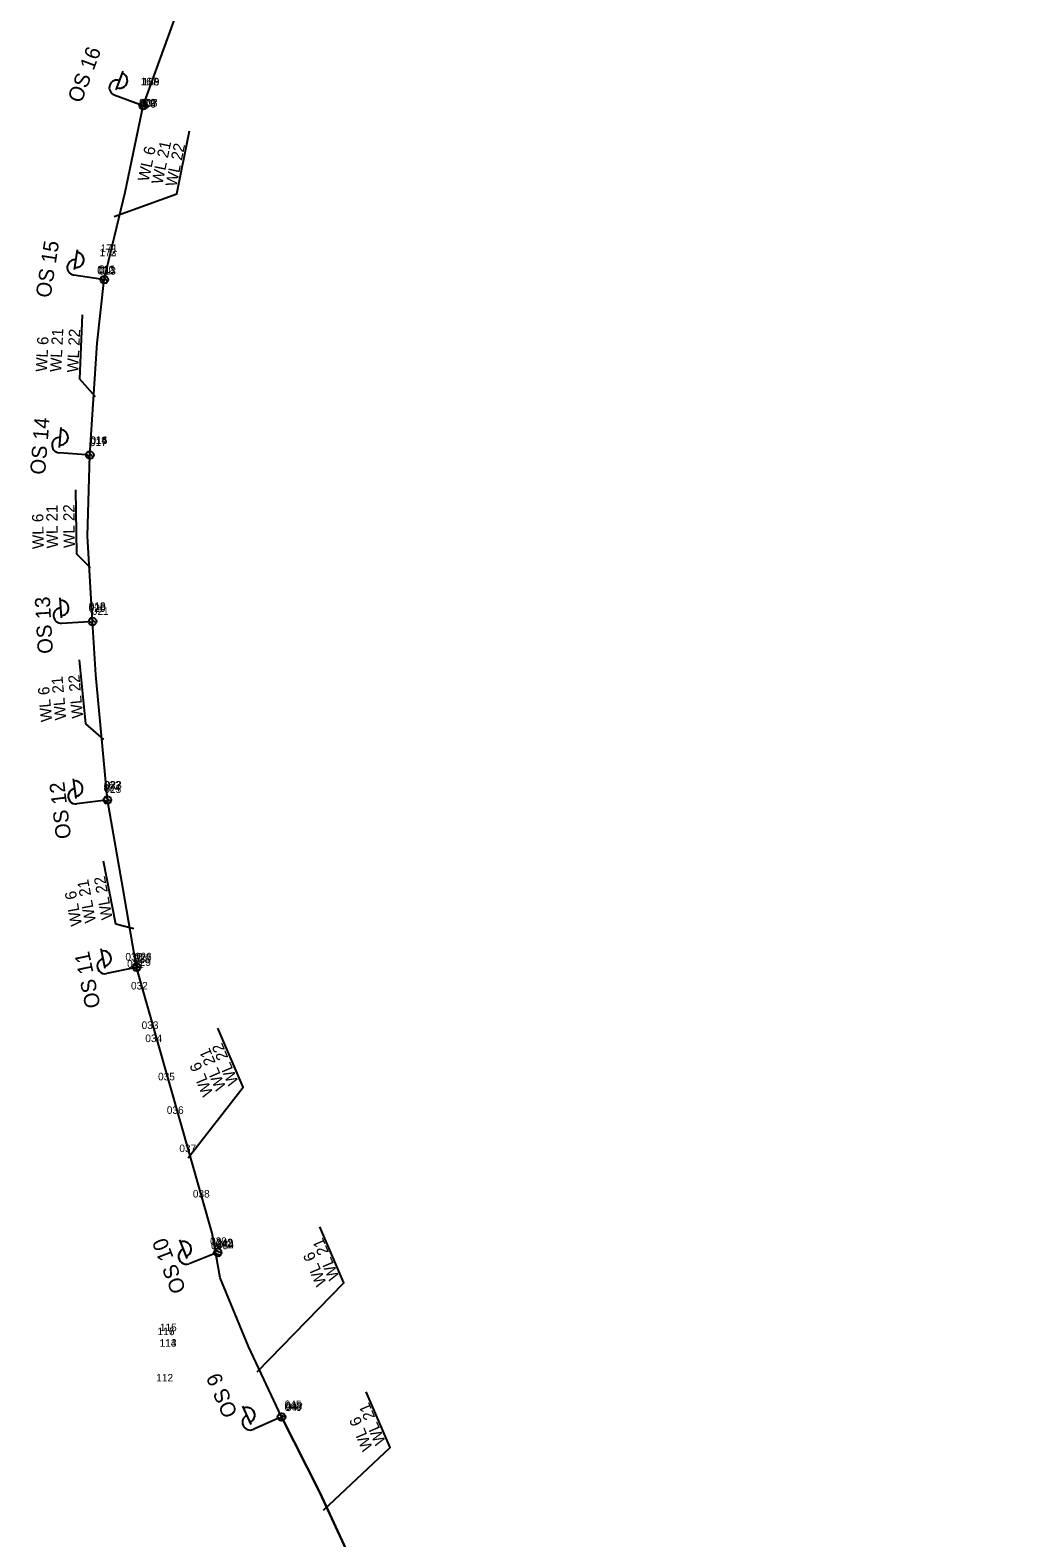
# Model space of a CAD drawing. Extents: x -695448 to -695200, y -1124997 to -1123857.
# Drawn here: x -695447.6 to -695315.9, y -1124800.8 to -1124601.1 of the extents above; entities that cross this region are included whole.
import ezdxf

# ---------------------------------------------------------------- set-up
doc = ezdxf.new("R2010")
doc.units = 0
doc.layers.add('Vrstva 26', color=7, linetype='Continuous')

msp = doc.modelspace()

# ---------------------------------------------------------------- linework, layer by layer
at = {"layer": 'Vrstva 26'}
for p, q in [((-695436.23, -1124608.98), (-695435.31, -1124606.48)), ((-695433.12, -1124610.89), (-695436.48, -1124609.65)), ((-695432.31, -1124611.45), (-695432.72, -1124610.56)), ((-695432.67, -1124611.58), (-695433.05, -1124610.76)), ((-695441.75, -1124632.79), (-695441.36, -1124630.17)), ((-695438.31, -1124634.03), (-695441.85, -1124633.5)), ((-695437.73, -1124634.61), (-695438.27, -1124633.89)), ((-695437.4, -1124634.41), (-695437.98, -1124633.63)), ((-695443.75, -1124656.33), (-695443.54, -1124653.68)), ((-695440.23, -1124657.32), (-695443.8, -1124657.04)), ((-695439.61, -1124657.85), (-695440.2, -1124657.17)), ((-695439.3, -1124657.63), (-695439.93, -1124656.89)), ((-695443.49, -1124678.94), (-695443.65, -1124676.28)), ((-695439.87, -1124679.43), (-695443.44, -1124679.65)), ((-695439.18, -1124679.87), (-695439.86, -1124679.28)), ((-695438.9, -1124679.61), (-695439.63, -1124678.96)), ((-695441.54, -1124702.87), (-695441.88, -1124700.23)), ((-695437.9, -1124703.12), (-695441.45, -1124703.58)), ((-695437.18, -1124703.52), (-695437.89, -1124702.97)), ((-695436.92, -1124703.24), (-695437.69, -1124702.64)), ((-695437.67, -1124725.36), (-695438.22, -1124722.76)), ((-695434.02, -1124725.32), (-695437.52, -1124726.06)), ((-695433.27, -1124725.66), (-695434.03, -1124725.17)), ((-695433.03, -1124725.36), (-695433.85, -1124724.83)), ((-695426.84, -1124763.82), (-695427.8, -1124761.34)), ((-695423.25, -1124763.2), (-695426.58, -1124764.49)), ((-695422.45, -1124763.41), (-695423.28, -1124763.05)), ((-695422.26, -1124763.08), (-695423.16, -1124762.68)), ((-695418.35, -1124785.79), (-695419.43, -1124783.36)), ((-695414.79, -1124784.99), (-695418.06, -1124786.44)), ((-695413.99, -1124785.17), (-695414.83, -1124784.85)), ((-695413.82, -1124784.83), (-695414.73, -1124784.48))]:
    msp.add_line(p, q, dxfattribs=at)
for points in [[(-695403.9, -1124806.39), (-695409.22, -1124794.8), (-695414.32, -1124784.79), (-695418.68, -1124775.48), (-695422.45, -1124766.38), (-695423.51, -1124760.43), (-695433.52, -1124725.21), (-695435.3, -1124714.9), (-695437.39, -1124703.05), (-695438.94, -1124686.49), (-695439.36, -1124679.4), (-695440.02, -1124668.1), (-695439.72, -1124657.36), (-695438.75, -1124642.55), (-695437.81, -1124634.11), (-695435.03, -1124622.54), (-695432.64, -1124611.07), (-695424.56, -1124588.76)], [(-695414.32, -1124784.79), (-695418.68, -1124775.48), (-695422.45, -1124766.38), (-695423.51, -1124760.43), (-695433.52, -1124725.21), (-695435.3, -1124714.9), (-695437.39, -1124703.05), (-695438.94, -1124686.49), (-695439.36, -1124679.4), (-695440.02, -1124668.1), (-695439.72, -1124657.36), (-695438.75, -1124642.55), (-695437.81, -1124634.11), (-695435.03, -1124622.54), (-695432.64, -1124611.07), (-695427.6, -1124597.21)], [(-695436.5, -1124625.75), (-695428.18, -1124622.75), (-695426.5, -1124614.4)], [(-695438.99, -1124649.64), (-695441.05, -1124647.29), (-695440.69, -1124638.78)], [(-695439.62, -1124672.31), (-695441.43, -1124670.48), (-695441.58, -1124661.95)], [(-695437.88, -1124695.03), (-695440.26, -1124692.97), (-695441.08, -1124684.49)], [(-695433.91, -1124720.13), (-695436.28, -1124719.52), (-695437.89, -1124711.15)], [(-695426.71, -1124750.47), (-695419.41, -1124741.12), (-695422.78, -1124733.29)], [(-695417.56, -1124778.83), (-695406.05, -1124767.02), (-695409.23, -1124759.62)], [(-695408.74, -1124797.17), (-695399.93, -1124788.85), (-695403.11, -1124781.45)], [(-695414.32, -1124784.79), (-695409.22, -1124794.8), (-695403.9, -1124806.39), (-695398.06, -1124816.61), (-695392.71, -1124827.57), (-695387.95, -1124836.45), (-695381.52, -1124848.94), (-695375.78, -1124858.72), (-695369.54, -1124870.95), (-695362.93, -1124881.95), (-695355.02, -1124896.53), (-695339.58, -1124927.79), (-695325.73, -1124960.98), (-695320.19, -1124976.48), (-695315.94, -1124994.16)]]:
    msp.add_lwpolyline(points, dxfattribs=at)
for centre in [(-695432.64, -1124611.07), (-695432.64, -1124611.07), (-695437.81, -1124634.11), (-695437.81, -1124634.11), (-695439.72, -1124657.36), (-695439.72, -1124657.36), (-695439.36, -1124679.4), (-695439.36, -1124679.4), (-695437.39, -1124703.05), (-695437.39, -1124703.05), (-695433.52, -1124725.21), (-695433.52, -1124725.21), (-695422.77, -1124763.01), (-695422.77, -1124763.01), (-695414.32, -1124784.79), (-695414.32, -1124784.79)]:
    msp.add_circle(centre, 0.511, dxfattribs=at)
for centre, start, end in [((-695436.12, -1124608.69), 69.7051, 249.7051), ((-695435.76, -1124607.74), 249.0025, 70.4077), ((-695441.54, -1124631.48), 260.821, 82.2262), ((-695441.7, -1124632.49), 81.5236, 261.5236), ((-695443.63, -1124655.01), 264.9139, 86.3191), ((-695443.72, -1124656.02), 85.6165, 265.6165), ((-695443.51, -1124678.63), 93.5976, 273.5976), ((-695443.56, -1124677.61), 272.8951, 94.3002), ((-695441.58, -1124702.56), 97.3675, 277.3675), ((-695441.7, -1124701.55), 276.665, 98.0701), ((-695437.73, -1124725.06), 101.9929, 281.9929), ((-695437.93, -1124724.06), 281.2903, 102.6955), ((-695427.31, -1124762.58), 290.4849, 111.89), ((-695426.95, -1124763.54), 111.1874, 291.1874), ((-695418.88, -1124784.57), 293.183, 114.5881), ((-695418.48, -1124785.51), 113.8855, 293.8855)]:
    msp.add_arc(centre, 1.02, start, end, dxfattribs=at)

# ---------------------------------------------------------------- texts
for s, height, rotation, p in [('OS 16', 2, 69.4105, (-695440.86, -1124610.82)), ('WL 6', 1.5, 78.2456, (-695431.93, -1124621.2)), ('WL 21', 1.5, 78.2456, (-695430.11, -1124621.57)), ('WL 22', 1.5, 78.2456, (-695428.26, -1124621.89)), ('OS 15', 2, 81.229, (-695444.94, -1124636.61)), ('WL 6', 1.5, 87.2226, (-695445.41, -1124646.36)), ('WL 21', 1.5, 87.2226, (-695443.51, -1124646.38)), ('WL 22', 1.5, 87.2226, (-695441.27, -1124646.46)), ('OS 14', 2, 85.3219, (-695445.66, -1124660.01)), ('WL 21', 1.5, 90.5967, (-695443.95, -1124669.71)), ('WL 22', 1.5, 90.5967, (-695441.7, -1124669.66)), ('WL 6', 1.5, 90.5967, (-695445.84, -1124669.8)), ('OS 13', 2, 93.303, (-695444.6, -1124683.63)), ('WL 6', 1.5, 95.1012, (-695444.71, -1124692.64)), ('WL 21', 1.5, 95.1012, (-695442.83, -1124692.4)), ('WL 22', 1.5, 95.1012, (-695440.6, -1124692.17)), ('OS 12', 2, 97.0729, (-695442.19, -1124708.09)), ('WL 21', 1.5, 100.4184, (-695438.9, -1124719.19)), ('WL 22', 1.5, 100.4184, (-695436.69, -1124718.76)), ('WL 6', 1.5, 100.4184, (-695440.75, -1124719.61)), ('OS 11', 2, 101.6983, (-695438.3, -1124730.42)), ('WL 21', 1.5, 112.8812, (-695421.63, -1124741.14)), ('WL 22', 1.5, 112.8812, (-695419.97, -1124740.46)), ('WL 6', 1.5, 112.8812, (-695423.35, -1124741.94)), ('OS 10', 2, 110.8928, (-695426.95, -1124767.99)), ('WL 21', 1.5, 112.8812, (-695406.62, -1124766.28)), ('WL 6', 1.5, 112.8812, (-695408.31, -1124767.09)), ('OS 9', 2, 113.5909, (-695420.1, -1124784.35)), ('WL 21', 1.5, 112.8812, (-695400.49, -1124788.12)), ('WL 6', 1.5, 112.8812, (-695402.19, -1124788.92))]:
    msp.add_text(s, height=height, rotation=rotation, dxfattribs=at).set_placement(p)
for s, p in [('167', (-695433, -1124608.35)), ('170', (-695432.78, -1124608.38)), ('168', (-695432.75, -1124608.38)), ('169', (-695432.73, -1124608.38)), ('006', (-695433.21, -1124611.34)), ('009', (-695433.19, -1124611.16)), ('007', (-695433, -1124611.21)), ('008', (-695432.98, -1124611.19)), ('172', (-695438.45, -1124631.02)), ('173', (-695438.45, -1124631.02)), ('171', (-695438.29, -1124630.45)), ('010', (-695438.74, -1124633.41)), ('012', (-695438.73, -1124633.28)), ('011', (-695438.51, -1124633.22)), ('013', (-695438.5, -1124633.44)), ('017', (-695439.7, -1124656.14)), ('014', (-695439.69, -1124655.87)), ('015', (-695439.64, -1124655.9)), ('016', (-695439.62, -1124655.9)), ('018', (-695439.87, -1124677.86)), ('020', (-695439.88, -1124678.13)), ('019', (-695439.85, -1124677.92)), ('021', (-695439.46, -1124678.53)), ('024', (-695437.92, -1124701.92)), ('022', (-695437.85, -1124701.55)), ('025', (-695437.8, -1124702.12)), ('023', (-695437.73, -1124701.57)), ('030', (-695435.01, -1124724.33)), ('031', (-695434.78, -1124725.27)), ('028', (-695433.95, -1124724.66)), ('029', (-695433.86, -1124725.04)), ('027', (-695433.81, -1124724.49)), ('026', (-695433.76, -1124724.3)), ('032', (-695434.27, -1124728.16)), ('033', (-695432.86, -1124733.39)), ('034', (-695432.37, -1124735.13)), ('035', (-695430.68, -1124740.2)), ('036', (-695429.52, -1124744.64)), ('037', (-695427.86, -1124749.71)), ('038', (-695426.07, -1124755.73)), ('039', (-695423.79, -1124762)), ('040', (-695423.66, -1124762.58)), ('041', (-695423.07, -1124762.44)), ('042', (-695423.02, -1124762.29)), ('043', (-695422.98, -1124762.17)), ('044', (-695422.82, -1124762.44)), ('117', (-695430.76, -1124773.96)), ('116', (-695430.73, -1124773.96)), ('115', (-695430.44, -1124773.43)), ('114', (-695430.49, -1124775.49)), ('113', (-695430.46, -1124775.49)), ('112', (-695430.92, -1124780.1)), ('046', (-695413.92, -1124783.99)), ('045', (-695413.9, -1124783.62)), ('048', (-695413.8, -1124783.82)), ('047', (-695413.71, -1124784.02))]:
    msp.add_text(s, height=1, dxfattribs=at).set_placement(p)

doc.saveas('drawing.dxf')
